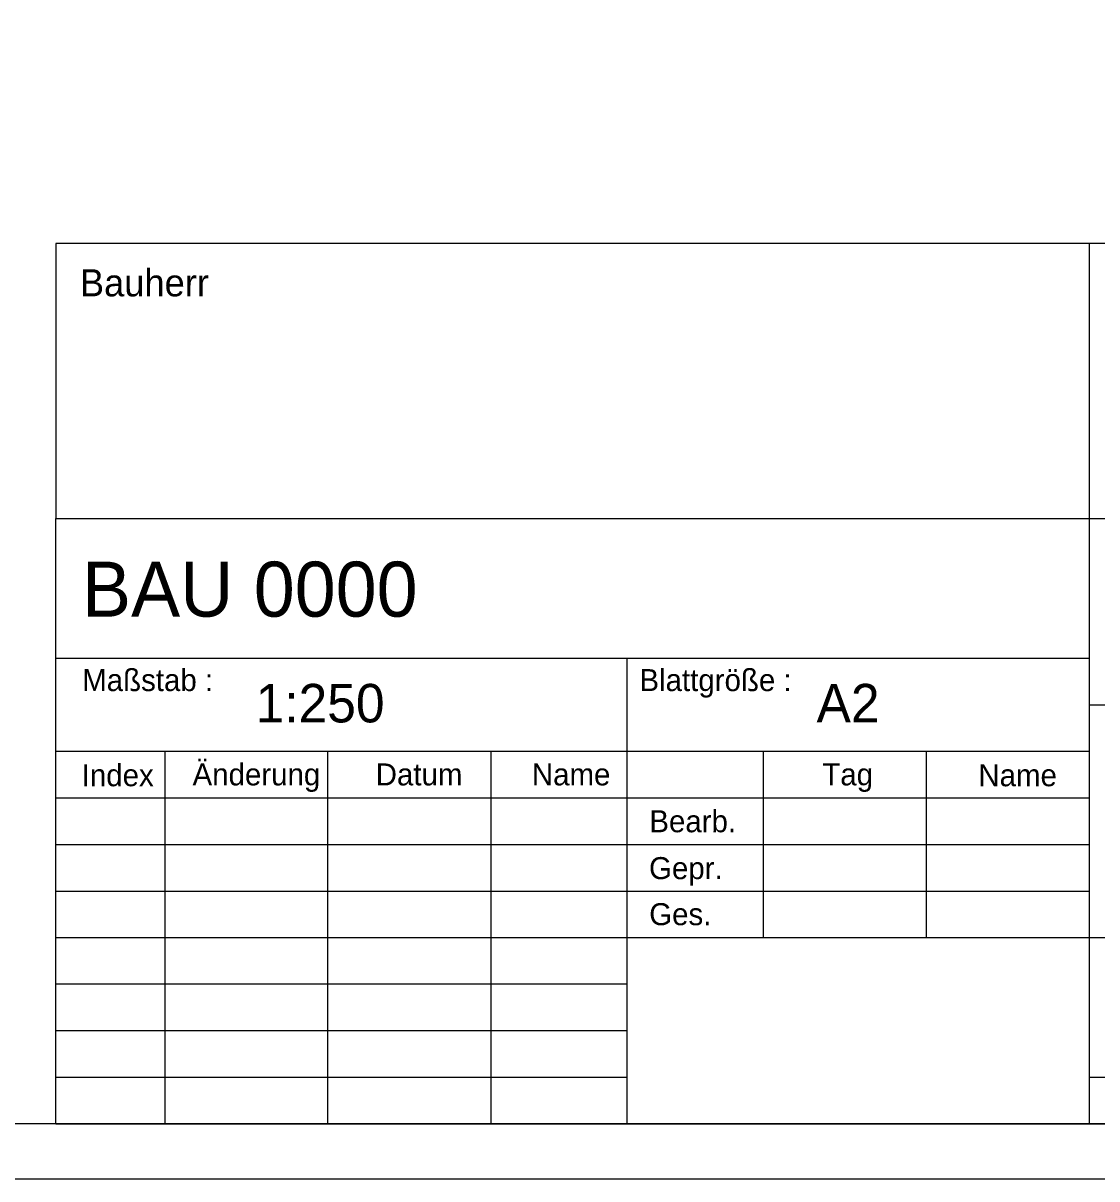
# Model space of a CAD drawing. Extents: x 0 to 148, y 0 to 105.
# Drawn here: x 102.04 to 126.41, y 0 to 26.25 of the extents above; entities that cross this region are included whole.
import ezdxf

# ---------------------------------------------------------------- set-up
doc = ezdxf.new("R2010")
doc.units = 0
doc.layers.add('90_Plankopf', color=7, linetype='Continuous')

msp = doc.modelspace()

# ---------------------------------------------------------------- linework, layer by layer
at = {"layer": '90_Plankopf'}
for p, q in [((147.25, 21.248), (102.78, 21.248)), ((102.78, 21.248), (102.78, 14.998)), ((126.25, 14.998), (126.25, 21.248)), ((102.78, 14.998), (147.25, 14.998)), ((102.78, 1.25), (102.78, 14.998)), ((102.78, 14.998), (147.25, 14.998)), ((126.25, 1.25), (126.25, 14.998)), ((102.78, 11.825), (126.25, 11.825)), ((115.751, 1.25), (115.751, 11.825)), ((126.25, 10.768), (147.25, 10.768)), ((102.78, 9.718), (126.25, 9.718)), ((105.251, 9.71), (105.251, 1.25)), ((108.957, 1.25), (108.957, 9.71)), ((112.662, 1.25), (112.662, 9.71)), ((118.839, 9.71), (118.839, 5.48)), ((122.544, 5.48), (122.544, 9.71)), ((102.78, 8.658), (126.25, 8.658)), ((102.78, 7.595), (126.25, 7.595)), ((102.78, 6.538), (126.25, 6.538)), ((102.78, 5.48), (126.25, 5.48)), ((102.78, 5.48), (126.25, 5.48)), ((115.751, 5.48), (126.25, 5.48)), ((126.25, 5.48), (147.25, 5.48)), ((115.751, 4.423), (102.78, 4.423)), ((115.751, 3.365), (102.78, 3.365)), ((102.78, 2.308), (115.751, 2.308)), ((126.25, 2.308), (147.25, 2.308)), ((147.25, 1.25), (102.78, 1.25)), ((102.78, 1.25), (115.751, 1.25)), ((105.7, 1.25), (147.25, 1.25)), ((105.7, 1.25), (147.25, 1.25))]:
    msp.add_line(p, q, dxfattribs=at)
for points in [[(0, 0), (148.5, 0), (148.5, 105), (0, 105)], [(6.25, 103.75), (147.25, 103.75), (147.25, 1.25), (6.25, 1.25)]]:
    msp.add_lwpolyline(points, close=True, dxfattribs=at)

# ---------------------------------------------------------------- texts
for s, height, p in [('Bauherr', 0.6159, (103.326, 20.044)), ('BAU 0000      ', 1.25, (103.373, 12.769)), ('Maßstab :', 0.5, (103.379, 11.079)), ('Blattgröße :', 0.49998, (116.029, 11.079)), ('1:250    ', 0.875, (107.315, 10.367)), ('A2       ', 0.875, (120.05, 10.367)), ('Änderung', 0.5, (105.884, 8.937)), ('Index', 0.5, (103.367, 8.918)), ('Datum', 0.5, (110.042, 8.937)), ('Name', 0.5, (113.587, 8.937)), ('Tag', 0.5, (120.181, 8.937)), ('Name', 0.5, (123.723, 8.918)), ('Bearb.', 0.5, (116.254, 7.873)), ('Gepr.', 0.5, (116.247, 6.808)), ('Ges.', 0.5, (116.251, 5.762))]:
    msp.add_text(s, height=height, dxfattribs=at).set_placement(p)

doc.saveas('drawing.dxf')
